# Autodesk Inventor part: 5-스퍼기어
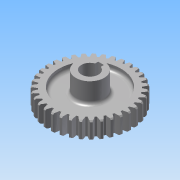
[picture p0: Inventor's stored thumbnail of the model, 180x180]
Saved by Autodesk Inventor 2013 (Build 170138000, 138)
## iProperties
Created: 2013-08
Part Number: 5-스퍼기어
Material: 강
Document SubType Name: Modeling
Designer: 한국산업디자인학원
Categories: <?xml version="1.0" encoding="UTF-16"?> <MemberInstance><Categories><FamilyTemplate><FamilyTemplateParameter ValueType="xs:double" Id="1" ObjectReferenceKey="da
Density: 1 g/cm^3
CustomPartVersion: 1
Author: 한국산업디자인학원
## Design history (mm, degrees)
sketch "Sketch1"
  geometry: C1 r 37 at (0, 0)
  constraints: 1 centre point
  dimensions: "d0" = 74 diameter of C1 (= da_da)
extrude "Extrusion1" new body sketch "Sketch1" distance "d1" = 15 (= da_b); taper "d2" = 0 deg
chamfer "모따기1" distance "d49" = 1; stored, may be unused: second distance "d50" = 2, angle "d51" = 45 deg
workplane "Work Plane2"
feature "피치 지름" dims "d4" = 10, "d5" = 0
workplane "Work Plane8"
workplane "Work Plane9"
feature "스퍼 기어" dims "da_b" = 15, "da_d" = 70, "da_aw" = 70, "da_da" = 74, "da_df" = 65, "da_dw" = 70, angle "da_beta" = 0 deg, "da_lefttooth" = 0, "da_righttooth" = 0
node "작업 평면11"
sketch "스케치3"
  geometry: C1 r 12.5 at (0, 0); 1 further point
  constraints: 1 centre point, 1 coincident
  dimensions: "d53" = 25 diameter of C1
extrude "돌출2" join sketch "스케치3" distance "d55" = 31; taper "d56" = 0 deg
sketch "스케치4"
  geometry: L1 (-2.5, 7.071)-(-2.5, 9.8); L2 (-2.5, 9.8)-(2.5, 9.8); L3 (2.5, 9.8)-(2.5, 7.071); C1 r 12.5 at (0, 0) reference; A1 r 7.5 centre (0, 0) between (-2.5, 7.071) and (2.5, 7.071)
  constraints: 6 end point, 2 parallel, 2 point on circle, 1 centre point, 1 coincident, 1 perpendicular, 1 vertical
  dimensions: "d57" = 15 diameter of A1; "d59" = 17.3 dimension on A1 L2; "d60" = 5 distance of L1.end L2.end
extrude "돌출3" cut sketch "스케치4" stored distance "d61" = 31; taper "d62" = 0 deg
sketch "스케치5"
  geometry: C1 r 12.5 at (0, 0) reference; C2 r 12.5 at (0, 0) reference; C3 r 12.5 at (0, 0); C4 r 27.5 at (0, 0)
  constraints: 2 centre point, 1 coincident, 1 concentric
  dimensions: "d63" = 55 diameter of C4
extrude "돌출4" cut sketch "스케치5" distance "d65" = 5; taper "d66" = 0 deg
node "작업 평면12"
fillet "모깎기1" dims "d67" = 3
body "Solid1"
mirror "대칭1"
sketch "Sketch2"
  geometry: C1 r 37 at (0, 0) reference; C2 r 35 at (0, 0)
  constraints: 1 centre point, 1 coincident
  dimensions: "d3" = 70 diameter of C2 (= da_dw)
body "Srf1"
other parameters: "d17" = 0, "d34" = 0.8976 (computed from da_z), "d39" = 0, "d41" = 0, "d47" = 0, "d48" = 0, "d52" = 3
